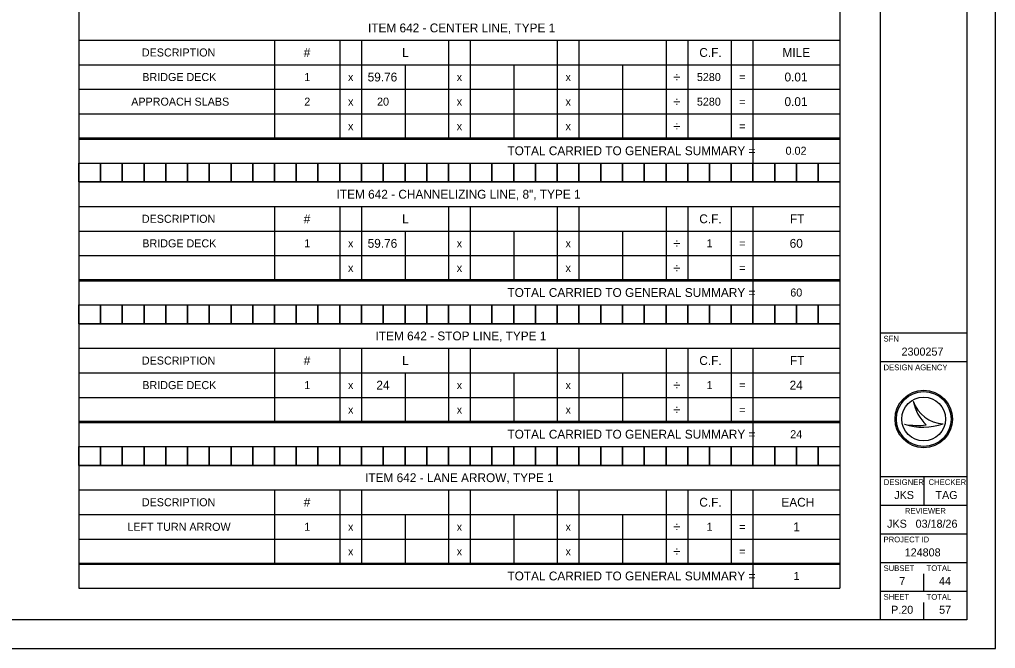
# Model space of a CAD drawing. Extents: x 0 to 34, y 0 to 22.
# Drawn here: x 17 to 34, y 0 to 10.96 of the extents above; entities that cross this region are included whole.
import ezdxf

# ---------------------------------------------------------------- set-up
doc = ezdxf.new("R2010")
doc.units = 0
for name, color, linetype in [('SH_Border', 7, 'Continuous'), ('SH_Cut_Line', 7, 'Continuous'), ('SH_Data', 7, 'Continuous'), ('SH_Text', 7, 'Continuous')]:
    doc.layers.add(name, color=color, linetype=linetype)

msp = doc.modelspace()

# ---------------------------------------------------------------- linework, layer by layer
at = {"layer": 'SH_Border'}
for p, q in [((32, 0.5), (32, 21.5)), ((32, 5.5), (33.5, 5.5)), ((32, 5), (33.5, 5)), ((32, 3), (33.5, 3)), ((32.75, 3), (32.75, 2.5)), ((32, 2.5), (33.5, 2.5)), ((32, 2), (33.5, 2)), ((32, 1.5), (33.5, 1.5)), ((32, 1), (33.5, 1))]:
    msp.add_line(p, q, dxfattribs=at)
msp.add_lwpolyline([(1.5, 21.5), (33.5, 21.5), (33.5, 0.5), (1.5, 0.5)], close=True, dxfattribs=at)
at = {"layer": 'SH_Cut_Line'}
msp.add_lwpolyline([(0, 0), (34, 0), (34, 22), (0, 22)], close=True, dxfattribs=at)
at = {"layer": 'SH_Data'}
for p, q in [((32.567, 4.31), (32.567, 4.31)), ((32.75, 4), (32.75, 4)), ((33.087, 3.919), (33.087, 3.919)), ((32.417, 3.91), (32.417, 3.91)), ((32.75, 1), (32.75, 1.3)), ((32.75, 0.5), (32.75, 0.8)), ((32.375, 0.675), (32.375, 0.675))]:
    msp.add_line(p, q, dxfattribs=at)
for radius in [0.5, 0.477, 0.477, 0.382]:
    msp.add_circle((32.75, 4), radius, dxfattribs=at)
for centre, radius, start, end in [((33.116, 4.498), 0.58, 198.9257, 198.9319), ((33.347, 4.47), 0.796, 191.6379, 191.6421), ((33.116, 4.498), 0.58, 198.9319, 267.1657), ((33.347, 4.47), 0.796, 191.6421, 226.0947), ((32.739, 4.87), 1.013, 251.4576, 290.0832), ((32.648, 5.154), 1.266, 259.4964, 259.4995), ((32.739, 4.87), 1.013, 251.4527, 251.4576), ((32.648, 5.154), 1.266, 259.4995, 276.6672)]:
    msp.add_arc(centre, radius, start, end, dxfattribs=at)
at = {"layer": 'SH_Text'}
for p, q in [((18.032, 11.8), (18.032, 8.879)), ((31.291, 11.8), (31.291, 8.879)), ((18.032, 10.603), (31.291, 10.603)), ((21.442, 10.603), (21.442, 8.901)), ((22.578, 10.603), (22.578, 8.901)), ((22.957, 10.603), (22.957, 8.901)), ((24.472, 10.603), (24.472, 8.901)), ((24.851, 10.603), (24.851, 8.901)), ((26.367, 10.603), (26.367, 8.901)), ((26.745, 10.603), (26.745, 8.901)), ((28.261, 10.603), (28.261, 8.901)), ((28.639, 10.603), (28.639, 8.901)), ((29.397, 10.603), (29.397, 8.901)), ((29.776, 10.603), (29.776, 8.901)), ((18.032, 10.175), (31.291, 10.175)), ((23.715, 10.175), (23.715, 8.901)), ((25.609, 10.175), (25.609, 8.901)), ((27.503, 10.175), (27.503, 8.901)), ((18.032, 9.747), (31.291, 9.747)), ((18.032, 9.318), (31.291, 9.318)), ((18.032, 8.901), (31.291, 8.901)), ((18.032, 8.901), (18.032, 6.408)), ((18.032, 8.879), (31.291, 8.879)), ((29.776, 8.879), (29.776, 8.462)), ((31.291, 8.901), (31.291, 6.408)), ((18.032, 8.462), (31.291, 8.462)), ((18.032, 8.132), (31.291, 8.132)), ((18.032, 7.704), (31.291, 7.704)), ((21.442, 7.704), (21.442, 6.43)), ((22.578, 7.704), (22.578, 6.43)), ((22.957, 7.704), (22.957, 6.43)), ((24.472, 7.704), (24.472, 6.43)), ((24.851, 7.704), (24.851, 6.43)), ((26.367, 7.704), (26.367, 6.43)), ((26.745, 7.704), (26.745, 6.43)), ((28.261, 7.704), (28.261, 6.43)), ((28.639, 7.704), (28.639, 6.43)), ((29.397, 7.704), (29.397, 6.43)), ((29.776, 7.704), (29.776, 6.43)), ((18.032, 7.276), (31.291, 7.276)), ((23.715, 7.276), (23.715, 6.43)), ((25.609, 7.276), (25.609, 6.43)), ((27.503, 7.276), (27.503, 6.43)), ((18.032, 6.848), (31.291, 6.848)), ((18.032, 6.43), (31.291, 6.43)), ((18.032, 6.43), (18.032, 3.938)), ((18.032, 6.408), (31.291, 6.408)), ((29.776, 6.408), (29.776, 5.991)), ((31.291, 6.43), (31.291, 3.938)), ((18.032, 5.991), (31.291, 5.991)), ((18.032, 5.662), (31.291, 5.662)), ((18.032, 5.234), (31.291, 5.234)), ((21.442, 5.234), (21.442, 3.96)), ((22.578, 5.234), (22.578, 3.96)), ((22.957, 5.234), (22.957, 3.96)), ((24.472, 5.234), (24.472, 3.96)), ((24.851, 5.234), (24.851, 3.96)), ((26.367, 5.234), (26.367, 3.96)), ((26.745, 5.234), (26.745, 3.96)), ((28.261, 5.234), (28.261, 3.96)), ((28.639, 5.234), (28.639, 3.96)), ((29.397, 5.234), (29.397, 3.96)), ((29.776, 5.234), (29.776, 3.96)), ((18.032, 4.805), (31.291, 4.805)), ((23.715, 4.805), (23.715, 3.96)), ((25.609, 4.805), (25.609, 3.96)), ((27.503, 4.805), (27.503, 3.96)), ((18.032, 4.377), (31.291, 4.377)), ((18.032, 3.96), (31.291, 3.96)), ((18.032, 3.96), (18.032, 1.467)), ((18.032, 3.938), (31.291, 3.938)), ((29.776, 3.938), (29.776, 3.521)), ((31.291, 3.96), (31.291, 1.467)), ((18.032, 3.521), (31.291, 3.521)), ((18.032, 3.191), (31.291, 3.191)), ((18.032, 2.763), (31.291, 2.763)), ((21.442, 2.763), (21.442, 1.489)), ((22.578, 2.763), (22.578, 1.489)), ((22.957, 2.763), (22.957, 1.489)), ((24.472, 2.763), (24.472, 1.489)), ((24.851, 2.763), (24.851, 1.489)), ((26.367, 2.763), (26.367, 1.489)), ((26.745, 2.763), (26.745, 1.489)), ((28.261, 2.763), (28.261, 1.489)), ((28.639, 2.763), (28.639, 1.489)), ((29.397, 2.763), (29.397, 1.489)), ((29.776, 2.763), (29.776, 1.489)), ((18.032, 2.335), (31.291, 2.335)), ((23.715, 2.335), (23.715, 1.489)), ((25.609, 2.335), (25.609, 1.489)), ((27.503, 2.335), (27.503, 1.489)), ((18.032, 1.906), (31.291, 1.906)), ((18.032, 1.489), (31.291, 1.489)), ((18.032, 1.489), (18.032, 1.05)), ((18.032, 1.467), (31.291, 1.467)), ((29.776, 1.467), (29.776, 1.05)), ((31.291, 1.489), (31.291, 1.05)), ((18.032, 1.05), (31.291, 1.05))]:
    msp.add_line(p, q, dxfattribs=at)
for points in [[(18.032, 8.462), (18.411, 8.462), (18.411, 8.132), (18.032, 8.132)], [(18.411, 8.462), (18.79, 8.462), (18.79, 8.132), (18.411, 8.132)], [(18.79, 8.462), (19.169, 8.462), (19.169, 8.132), (18.79, 8.132)], [(19.169, 8.462), (19.548, 8.462), (19.548, 8.132), (19.169, 8.132)], [(19.548, 8.462), (19.927, 8.462), (19.927, 8.132), (19.548, 8.132)], [(19.927, 8.462), (20.305, 8.462), (20.305, 8.132), (19.927, 8.132)], [(20.305, 8.462), (20.684, 8.462), (20.684, 8.132), (20.305, 8.132)], [(20.684, 8.462), (21.063, 8.462), (21.063, 8.132), (20.684, 8.132)], [(21.063, 8.462), (21.442, 8.462), (21.442, 8.132), (21.063, 8.132)], [(21.442, 8.462), (21.821, 8.462), (21.821, 8.132), (21.442, 8.132)], [(21.821, 8.462), (22.199, 8.462), (22.199, 8.132), (21.821, 8.132)], [(22.199, 8.462), (22.578, 8.462), (22.578, 8.132), (22.199, 8.132)], [(22.578, 8.462), (22.957, 8.462), (22.957, 8.132), (22.578, 8.132)], [(22.957, 8.462), (23.336, 8.462), (23.336, 8.132), (22.957, 8.132)], [(23.336, 8.462), (23.715, 8.462), (23.715, 8.132), (23.336, 8.132)], [(23.715, 8.462), (24.094, 8.462), (24.094, 8.132), (23.715, 8.132)], [(24.094, 8.462), (24.472, 8.462), (24.472, 8.132), (24.094, 8.132)], [(24.472, 8.462), (24.851, 8.462), (24.851, 8.132), (24.472, 8.132)], [(24.851, 8.462), (25.23, 8.462), (25.23, 8.132), (24.851, 8.132)], [(25.23, 8.462), (25.609, 8.462), (25.609, 8.132), (25.23, 8.132)], [(25.609, 8.462), (25.988, 8.462), (25.988, 8.132), (25.609, 8.132)], [(25.988, 8.462), (26.367, 8.462), (26.367, 8.132), (25.988, 8.132)], [(26.367, 8.462), (26.745, 8.462), (26.745, 8.132), (26.367, 8.132)], [(26.745, 8.462), (27.124, 8.462), (27.124, 8.132), (26.745, 8.132)], [(27.124, 8.462), (27.503, 8.462), (27.503, 8.132), (27.124, 8.132)], [(27.503, 8.462), (27.882, 8.462), (27.882, 8.132), (27.503, 8.132)], [(27.882, 8.462), (28.261, 8.462), (28.261, 8.132), (27.882, 8.132)], [(28.261, 8.462), (28.639, 8.462), (28.639, 8.132), (28.261, 8.132)], [(28.639, 8.462), (29.018, 8.462), (29.018, 8.132), (28.639, 8.132)], [(29.018, 8.462), (29.397, 8.462), (29.397, 8.132), (29.018, 8.132)], [(29.397, 8.462), (29.776, 8.462), (29.776, 8.132), (29.397, 8.132)], [(29.776, 8.462), (30.155, 8.462), (30.155, 8.132), (29.776, 8.132)], [(30.155, 8.462), (30.534, 8.462), (30.534, 8.132), (30.155, 8.132)], [(30.534, 8.462), (30.912, 8.462), (30.912, 8.132), (30.534, 8.132)], [(30.912, 8.462), (31.291, 8.462), (31.291, 8.132), (30.912, 8.132)], [(18.032, 5.991), (18.411, 5.991), (18.411, 5.662), (18.032, 5.662)], [(18.411, 5.991), (18.79, 5.991), (18.79, 5.662), (18.411, 5.662)], [(18.79, 5.991), (19.169, 5.991), (19.169, 5.662), (18.79, 5.662)], [(19.169, 5.991), (19.548, 5.991), (19.548, 5.662), (19.169, 5.662)], [(19.548, 5.991), (19.927, 5.991), (19.927, 5.662), (19.548, 5.662)], [(19.927, 5.991), (20.305, 5.991), (20.305, 5.662), (19.927, 5.662)], [(20.305, 5.991), (20.684, 5.991), (20.684, 5.662), (20.305, 5.662)], [(20.684, 5.991), (21.063, 5.991), (21.063, 5.662), (20.684, 5.662)], [(21.063, 5.991), (21.442, 5.991), (21.442, 5.662), (21.063, 5.662)], [(21.442, 5.991), (21.821, 5.991), (21.821, 5.662), (21.442, 5.662)], [(21.821, 5.991), (22.199, 5.991), (22.199, 5.662), (21.821, 5.662)], [(22.199, 5.991), (22.578, 5.991), (22.578, 5.662), (22.199, 5.662)], [(22.578, 5.991), (22.957, 5.991), (22.957, 5.662), (22.578, 5.662)], [(22.957, 5.991), (23.336, 5.991), (23.336, 5.662), (22.957, 5.662)], [(23.336, 5.991), (23.715, 5.991), (23.715, 5.662), (23.336, 5.662)], [(23.715, 5.991), (24.094, 5.991), (24.094, 5.662), (23.715, 5.662)], [(24.094, 5.991), (24.472, 5.991), (24.472, 5.662), (24.094, 5.662)], [(24.472, 5.991), (24.851, 5.991), (24.851, 5.662), (24.472, 5.662)], [(24.851, 5.991), (25.23, 5.991), (25.23, 5.662), (24.851, 5.662)], [(25.23, 5.991), (25.609, 5.991), (25.609, 5.662), (25.23, 5.662)], [(25.609, 5.991), (25.988, 5.991), (25.988, 5.662), (25.609, 5.662)], [(25.988, 5.991), (26.367, 5.991), (26.367, 5.662), (25.988, 5.662)], [(26.367, 5.991), (26.745, 5.991), (26.745, 5.662), (26.367, 5.662)], [(26.745, 5.991), (27.124, 5.991), (27.124, 5.662), (26.745, 5.662)], [(27.124, 5.991), (27.503, 5.991), (27.503, 5.662), (27.124, 5.662)], [(27.503, 5.991), (27.882, 5.991), (27.882, 5.662), (27.503, 5.662)], [(27.882, 5.991), (28.261, 5.991), (28.261, 5.662), (27.882, 5.662)], [(28.261, 5.991), (28.639, 5.991), (28.639, 5.662), (28.261, 5.662)], [(28.639, 5.991), (29.018, 5.991), (29.018, 5.662), (28.639, 5.662)], [(29.018, 5.991), (29.397, 5.991), (29.397, 5.662), (29.018, 5.662)], [(29.397, 5.991), (29.776, 5.991), (29.776, 5.662), (29.397, 5.662)], [(29.776, 5.991), (30.155, 5.991), (30.155, 5.662), (29.776, 5.662)], [(30.155, 5.991), (30.534, 5.991), (30.534, 5.662), (30.155, 5.662)], [(30.534, 5.991), (30.912, 5.991), (30.912, 5.662), (30.534, 5.662)], [(30.912, 5.991), (31.291, 5.991), (31.291, 5.662), (30.912, 5.662)], [(18.032, 3.521), (18.411, 3.521), (18.411, 3.191), (18.032, 3.191)], [(18.411, 3.521), (18.79, 3.521), (18.79, 3.191), (18.411, 3.191)], [(18.79, 3.521), (19.169, 3.521), (19.169, 3.191), (18.79, 3.191)], [(19.169, 3.521), (19.548, 3.521), (19.548, 3.191), (19.169, 3.191)], [(19.548, 3.521), (19.927, 3.521), (19.927, 3.191), (19.548, 3.191)], [(19.927, 3.521), (20.305, 3.521), (20.305, 3.191), (19.927, 3.191)], [(20.305, 3.521), (20.684, 3.521), (20.684, 3.191), (20.305, 3.191)], [(20.684, 3.521), (21.063, 3.521), (21.063, 3.191), (20.684, 3.191)], [(21.063, 3.521), (21.442, 3.521), (21.442, 3.191), (21.063, 3.191)], [(21.442, 3.521), (21.821, 3.521), (21.821, 3.191), (21.442, 3.191)], [(21.821, 3.521), (22.199, 3.521), (22.199, 3.191), (21.821, 3.191)], [(22.199, 3.521), (22.578, 3.521), (22.578, 3.191), (22.199, 3.191)], [(22.578, 3.521), (22.957, 3.521), (22.957, 3.191), (22.578, 3.191)], [(22.957, 3.521), (23.336, 3.521), (23.336, 3.191), (22.957, 3.191)], [(23.336, 3.521), (23.715, 3.521), (23.715, 3.191), (23.336, 3.191)], [(23.715, 3.521), (24.094, 3.521), (24.094, 3.191), (23.715, 3.191)], [(24.094, 3.521), (24.472, 3.521), (24.472, 3.191), (24.094, 3.191)], [(24.472, 3.521), (24.851, 3.521), (24.851, 3.191), (24.472, 3.191)], [(24.851, 3.521), (25.23, 3.521), (25.23, 3.191), (24.851, 3.191)], [(25.23, 3.521), (25.609, 3.521), (25.609, 3.191), (25.23, 3.191)], [(25.609, 3.521), (25.988, 3.521), (25.988, 3.191), (25.609, 3.191)], [(25.988, 3.521), (26.367, 3.521), (26.367, 3.191), (25.988, 3.191)], [(26.367, 3.521), (26.745, 3.521), (26.745, 3.191), (26.367, 3.191)], [(26.745, 3.521), (27.124, 3.521), (27.124, 3.191), (26.745, 3.191)], [(27.124, 3.521), (27.503, 3.521), (27.503, 3.191), (27.124, 3.191)], [(27.503, 3.521), (27.882, 3.521), (27.882, 3.191), (27.503, 3.191)], [(27.882, 3.521), (28.261, 3.521), (28.261, 3.191), (27.882, 3.191)], [(28.261, 3.521), (28.639, 3.521), (28.639, 3.191), (28.261, 3.191)], [(28.639, 3.521), (29.018, 3.521), (29.018, 3.191), (28.639, 3.191)], [(29.018, 3.521), (29.397, 3.521), (29.397, 3.191), (29.018, 3.191)], [(29.397, 3.521), (29.776, 3.521), (29.776, 3.191), (29.397, 3.191)], [(29.776, 3.521), (30.155, 3.521), (30.155, 3.191), (29.776, 3.191)], [(30.155, 3.521), (30.534, 3.521), (30.534, 3.191), (30.155, 3.191)], [(30.534, 3.521), (30.912, 3.521), (30.912, 3.191), (30.534, 3.191)], [(30.912, 3.521), (31.291, 3.521), (31.291, 3.191), (30.912, 3.191)]]:
    msp.add_lwpolyline(points, close=True, dxfattribs=at)

# ---------------------------------------------------------------- texts
at = {"layer": 'SH_Data'}
for s, height, p in [('SFN', 0.1, (32.05, 5.35)), ('2300257', 0.14, (32.364, 5.105)), ('DESIGN AGENCY', 0.1, (32.05, 4.85)), ('DESIGNER', 0.1, (32.054, 2.85)), ('CHECKER', 0.1, (32.835, 2.85)), ('JKS', 0.14, (32.237, 2.605)), ('TAG', 0.14, (32.955, 2.605)), ('REVIEWER', 0.1, (32.422, 2.35)), ('JKS', 0.14, (32.112, 2.105)), ('03/18/26', 0.14, (32.609, 2.105)), ('PROJECT ID', 0.1, (32.05, 1.85)), ('124808', 0.14, (32.419, 1.605)), ('SUBSET', 0.1, (32.05, 1.35)), ('TOTAL', 0.1, (32.8, 1.35)), ('7', 0.14, (32.324, 1.105)), ('44', 0.14, (33.016, 1.105)), ('SHEET', 0.1, (32.05, 0.85)), ('TOTAL', 0.1, (32.8, 0.85)), ('P.20', 0.14, (32.182, 0.605)), ('57', 0.14, (33.018, 0.605))]:
    msp.add_text(s, height=height, dxfattribs=at).set_placement(p)
at = {"layer": 'SH_Text'}
for s, height, p in [('ITEM 642 - CENTER LINE, TYPE 1', 0.154, (23.07, 10.74)), ('DESCRIPTION', 0.14, (19.131, 10.319)), ('#', 0.154, (21.951, 10.312)), ('L', 0.154, (23.664, 10.312)), ('C.F.', 0.154, (28.841, 10.312)), ('MILE', 0.154, (30.29, 10.312)), ('BRIDGE DECK', 0.14, (19.139, 9.891)), ('1', 0.14, (21.96, 9.891)), ('59.76', 0.154, (23.064, 9.884)), ('5280', 0.14, (28.799, 9.891)), ('0.01', 0.154, (30.325, 9.884)), ('x', 0.14, (22.722, 9.891)), ('x', 0.14, (24.616, 9.891)), ('x', 0.14, (26.511, 9.891)), ('÷', 0.168, (28.388, 9.877)), ('=', 0.14, (29.537, 9.891)), ('APPROACH SLABS', 0.14, (18.946, 9.462)), ('2', 0.14, (21.96, 9.462)), ('x', 0.14, (22.722, 9.462)), ('20', 0.14, (23.228, 9.462)), ('x', 0.14, (24.616, 9.462)), ('x', 0.14, (26.511, 9.462)), ('÷', 0.168, (28.388, 9.448)), ('5280', 0.14, (28.799, 9.462)), ('=', 0.14, (29.537, 9.462)), ('0.01', 0.154, (30.325, 9.455)), ('x', 0.14, (22.722, 9.034)), ('x', 0.14, (24.616, 9.034)), ('x', 0.14, (26.511, 9.034)), ('÷', 0.168, (28.388, 9.02)), ('=', 0.14, (29.537, 9.034)), ('TOTAL CARRIED TO GENERAL SUMMARY =', 0.154, (25.499, 8.599)), ('0.02', 0.14, (30.344, 8.606)), ('ITEM 642 - CHANNELIZING LINE, 8", TYPE 1', 0.154, (22.523, 7.841)), ('DESCRIPTION', 0.14, (19.131, 7.42)), ('#', 0.154, (21.951, 7.413)), ('L', 0.154, (23.664, 7.413)), ('C.F.', 0.154, (28.841, 7.413)), ('FT', 0.154, (30.419, 7.413)), ('59.76', 0.154, (23.064, 6.985)), ('60', 0.154, (30.415, 6.985)), ('BRIDGE DECK', 0.14, (19.139, 6.992)), ('1', 0.14, (21.96, 6.992)), ('x', 0.14, (22.722, 6.992)), ('x', 0.14, (24.616, 6.992)), ('x', 0.14, (26.511, 6.992)), ('÷', 0.168, (28.388, 6.978)), ('1', 0.14, (28.968, 6.992)), ('=', 0.14, (29.537, 6.992)), ('x', 0.14, (22.722, 6.564)), ('x', 0.14, (24.616, 6.564)), ('x', 0.14, (26.511, 6.564)), ('÷', 0.168, (28.388, 6.55)), ('=', 0.14, (29.537, 6.564)), ('TOTAL CARRIED TO GENERAL SUMMARY =', 0.154, (25.499, 6.128)), ('60', 0.14, (30.426, 6.135)), ('ITEM 642 - STOP LINE, TYPE 1', 0.154, (23.202, 5.371)), ('DESCRIPTION', 0.14, (19.131, 4.949)), ('#', 0.154, (21.951, 4.942)), ('L', 0.154, (23.664, 4.942)), ('C.F.', 0.154, (28.841, 4.942)), ('FT', 0.154, (30.419, 4.942)), ('BRIDGE DECK', 0.14, (19.139, 4.521)), ('1', 0.14, (21.96, 4.521)), ('x', 0.14, (22.722, 4.521)), ('24', 0.154, (23.216, 4.514)), ('x', 0.14, (24.616, 4.521)), ('x', 0.14, (26.511, 4.521)), ('÷', 0.168, (28.388, 4.507)), ('1', 0.14, (28.968, 4.521)), ('=', 0.14, (29.537, 4.521)), ('24', 0.154, (30.414, 4.514)), ('x', 0.14, (22.722, 4.093)), ('x', 0.14, (24.616, 4.093)), ('x', 0.14, (26.511, 4.093)), ('÷', 0.168, (28.388, 4.079)), ('=', 0.14, (29.537, 4.093)), ('TOTAL CARRIED TO GENERAL SUMMARY =', 0.154, (25.499, 3.658)), ('24', 0.14, (30.425, 3.665)), ('ITEM 642 - LANE ARROW, TYPE 1', 0.154, (23.02, 2.9)), ('DESCRIPTION', 0.14, (19.131, 2.479)), ('#', 0.154, (21.951, 2.472)), ('C.F.', 0.154, (28.841, 2.472)), ('EACH', 0.154, (30.271, 2.472)), ('LEFT TURN ARROW', 0.14, (18.878, 2.051)), ('1', 0.14, (21.96, 2.051)), ('x', 0.14, (22.722, 2.051)), ('x', 0.14, (24.616, 2.051)), ('x', 0.14, (26.511, 2.051)), ('÷', 0.168, (28.388, 2.037)), ('1', 0.14, (28.968, 2.051)), ('=', 0.14, (29.537, 2.051)), ('1', 0.154, (30.479, 2.044)), ('x', 0.14, (22.722, 1.622)), ('x', 0.14, (24.616, 1.622)), ('x', 0.14, (26.511, 1.622)), ('÷', 0.168, (28.388, 1.608)), ('=', 0.14, (29.537, 1.622)), ('TOTAL CARRIED TO GENERAL SUMMARY =', 0.154, (25.499, 1.187)), ('1', 0.14, (30.484, 1.194))]:
    msp.add_text(s, height=height, dxfattribs=at).set_placement(p)

doc.saveas('drawing.dxf')
